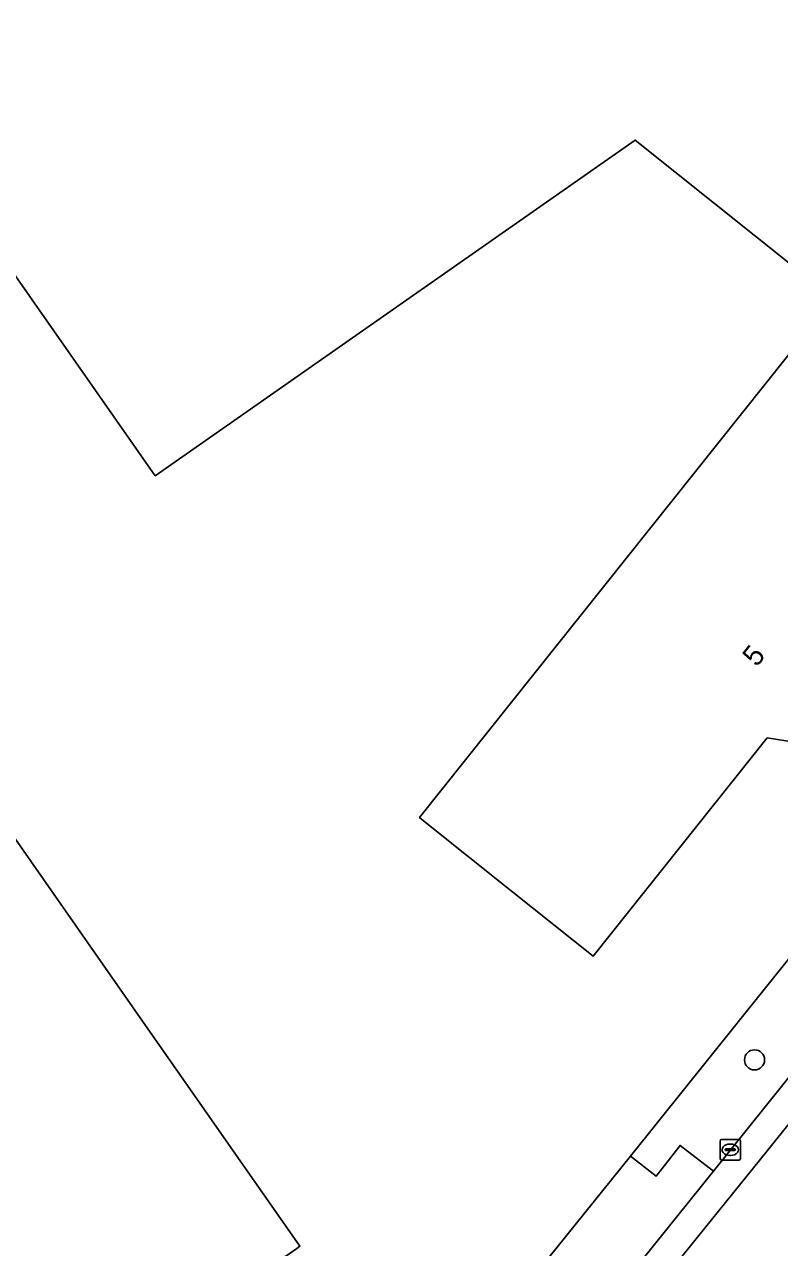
# Model space of a CAD drawing. Extents: x 156702 to 158052, y 387630 to 388992.
# Drawn here: x 157361.6 to 157398.4, y 388126 to 388185.6 of the extents above; entities that cross this region are included whole.
import ezdxf

# ---------------------------------------------------------------- set-up
doc = ezdxf.new("R2010")
doc.units = 0
for name, color, linetype in [('IMGEO_Berm_groen', 7, 'Continuous'), ('IMGEO_Boom', 7, 'Continuous'), ('IMGEO_Erf', 7, 'Continuous'), ('IMGEO_Kolk', 7, 'Continuous'), ('IMGEO_Pand', 7, 'Continuous'), ('IMGEO_Pand_nummerreeks', 7, 'Continuous'), ('IMGEO_Rijbaan_lokaal_gesloten', 7, 'Continuous'), ('IMGEO_Rijbaan_lokaal_open', 7, 'Continuous')]:
    doc.layers.add(name, color=color, linetype=linetype)

msp = doc.modelspace()

# ---------------------------------------------------------------- linework, layer by layer
at = {"layer": 'IMGEO_Berm_groen'}
msp.add_lwpolyline([(157406.909, 388144.334), (157404.098, 388146.633), (157391.144, 388130.462), (157392.39, 388129.493), (157393.555, 388130.997), (157395.189, 388129.737)], close=True, dxfattribs=at)
at = {"layer": 'IMGEO_Boom'}
msp.add_circle((157397.185, 388135.16), 0.489, dxfattribs=at)
at = {"layer": 'IMGEO_Erf'}
msp.add_lwpolyline([(157304.594, 388111.931), (157309.704, 388107.668), (157345.604, 388078.857), (157350.282, 388079.607), (157353.239, 388083.252), (157357.392, 388088.42), (157376.693, 388112.497), (157380.893, 388117.749), (157391.144, 388130.462), (157404.098, 388146.633), (157406.558, 388149.7), (157418.329, 388164.322), (157428.032, 388175.523), (157430.343, 388177.94), (157441.633, 388189.119), (157442.935, 388190.379), (157453.889, 388200.705), (157463.105, 388209.35), (157478.926, 388224.264), (157484.402, 388229.388), (157504.128, 388247.959), (157518.512, 388268.247), (157504.449, 388292.394)], dxfattribs=at)
for points in [[(157382.689, 388213.993), (157413.658, 388170.639), (157409.549, 388165.599), (157401.065, 388154.956), (157401.605, 388153.623), (157399.217, 388150.627), (157397.804, 388150.856), (157389.325, 388140.219), (157385.415, 388143.336), (157381.144, 388146.742), (157380.869, 388146.961), (157401.032, 388172.254), (157391.362, 388179.963), (157367.988, 388163.613), (157349.155, 388190.537)], [(157351.143, 388160.273), (157367.369, 388137.046), (157375.029, 388126.081), (157374.884, 388125.98), (157371, 388123.278), (157373.931, 388119.066), (157374.291, 388118.549), (157359.447, 388108.199), (157357.92, 388110.389), (157354.876, 388108.287), (157356.429, 388106.057), (157338.379, 388093.469), (157327.058, 388109.73), (157327.201, 388109.843), (157311.351, 388132.544), (157338.607, 388151.537)]]:
    msp.add_lwpolyline(points, close=True, dxfattribs=at)
at = {"layer": 'IMGEO_Kolk'}
for p, q in [((157395.503, 388130.356), (157395.503, 388131.208)), ((157395.578, 388131.282), (157396.43, 388131.282)), ((157395.991, 388131.062), (157396.016, 388131.062)), ((157396.504, 388131.208), (157396.504, 388130.356)), ((157395.762, 388130.776), (157395.762, 388130.788)), ((157396.2, 388130.739), (157395.802, 388130.739)), ((157395.805, 388130.825), (157396.203, 388130.825)), ((157396.014, 388130.502), (157395.989, 388130.502)), ((157396.246, 388130.788), (157396.246, 388130.776)), ((157396.43, 388130.282), (157395.578, 388130.282))]:
    msp.add_line(p, q, dxfattribs=at)
for points in [[(157395.503, 388130.356), (157395.503, 388131.208)], [(157395.578, 388131.282), (157396.43, 388131.282)], [(157396.504, 388131.208), (157396.504, 388130.356)], [(157396.43, 388130.282), (157395.578, 388130.282)]]:
    msp.add_lwpolyline(points, dxfattribs=at)
for centre, radius, start, end in [((157395.58, 388131.206), 0.0765, 91.55205, 178.44795), ((157395.58, 388131.206), 0.0765, 91.55205, 178.44795), ((157396.428, 388131.206), 0.0765, 1.55205, 88.44795), ((157396.428, 388131.206), 0.0765, 1.55205, 88.44795), ((157395.802, 388130.785), 0.0403, 85.87752, 175.75265), ((157395.799, 388130.775), 0.0366, 178.93798, 274.71019), ((157396.203, 388130.782), 0.043, 264.86636, 352.45326), ((157396.207, 388130.787), 0.0386, 1.73085, 96.63898), ((157395.58, 388130.358), 0.0765, 181.55205, 268.44795), ((157395.58, 388130.358), 0.0765, 181.55205, 268.44795), ((157396.428, 388130.358), 0.0765, 271.55205, 358.44795), ((157396.428, 388130.358), 0.0765, 271.55205, 358.44795)]:
    msp.add_arc(centre, radius, start, end, dxfattribs=at)
for centre, major_axis, ratio, start_param, end_param in [((157395.99, 388130.782), (-0.387, 0.002), 0.722429, 4.712389, 7.853982), ((157396.015, 388130.782), (-0.39, 0.002), 0.717154, 1.570796, 4.712389)]:
    msp.add_ellipse(centre, major_axis=major_axis, ratio=ratio, start_param=start_param, end_param=end_param, dxfattribs=at)
at = {"layer": 'IMGEO_Pand'}
for points in [[(157391.362, 388179.963), (157401.032, 388172.254), (157380.869, 388146.961), (157381.144, 388146.742), (157385.415, 388143.336), (157389.325, 388140.219), (157397.804, 388150.856), (157399.217, 388150.627), (157401.605, 388153.623), (157401.065, 388154.956), (157409.549, 388165.599), (157413.658, 388170.639), (157382.689, 388213.993), (157349.155, 388190.537), (157367.988, 388163.613)], [(157371, 388123.278), (157374.884, 388125.98), (157375.029, 388126.081), (157367.369, 388137.046), (157351.143, 388160.273), (157338.607, 388151.537), (157311.351, 388132.544), (157327.201, 388109.843), (157327.058, 388109.73), (157338.379, 388093.469), (157356.429, 388106.057), (157354.876, 388108.287), (157357.92, 388110.389), (157359.447, 388108.199), (157374.291, 388118.549), (157373.931, 388119.066)]]:
    msp.add_lwpolyline(points, close=True, dxfattribs=at)
at = {"layer": 'IMGEO_Rijbaan_lokaal_gesloten'}
for points in [[(157372.577, 388099.512), (157397.82, 388130.747), (157409.349, 388145.114), (157418.054, 388155.99), (157428.31, 388168.424), (157433.998, 388174.762), (157442.081, 388182.987), (157451.011, 388191.483), (157458.709, 388198.857), (157466.448, 388206.061), (157472.586, 388211.776), (157482.524, 388221.195), (157508.983, 388245.953), (157519.658, 388255.905)], [(157519.658, 388255.905), (157508.983, 388245.953), (157482.524, 388221.195), (157472.586, 388211.776), (157466.448, 388206.061), (157458.709, 388198.857), (157451.011, 388191.483), (157442.081, 388182.987), (157433.998, 388174.762), (157428.31, 388168.424), (157418.054, 388155.99), (157409.349, 388145.114), (157397.82, 388130.747), (157372.577, 388099.512)], [(157425.667, 388167.547), (157419.954, 388160.554), (157409.376, 388147.415), (157406.909, 388144.334), (157395.189, 388129.737), (157378.344, 388108.801), (157361.36, 388087.666), (157355.149, 388079.934), (157354.447, 388079.064)]]:
    msp.add_lwpolyline(points, dxfattribs=at)
at = {"layer": 'IMGEO_Rijbaan_lokaal_open'}
msp.add_lwpolyline([(157376.693, 388112.497), (157377.891, 388111.57), (157376.726, 388110.062), (157378.344, 388108.801), (157395.189, 388129.737), (157393.555, 388130.997), (157392.39, 388129.493), (157391.144, 388130.462), (157380.893, 388117.749)], close=True, dxfattribs=at)

# ---------------------------------------------------------------- texts
at = {"layer": 'IMGEO_Pand_nummerreeks'}
msp.add_text('5', height=1, rotation=51.45161, dxfattribs=at).set_placement((157397.294, 388154.264))

doc.saveas('drawing.dxf')
